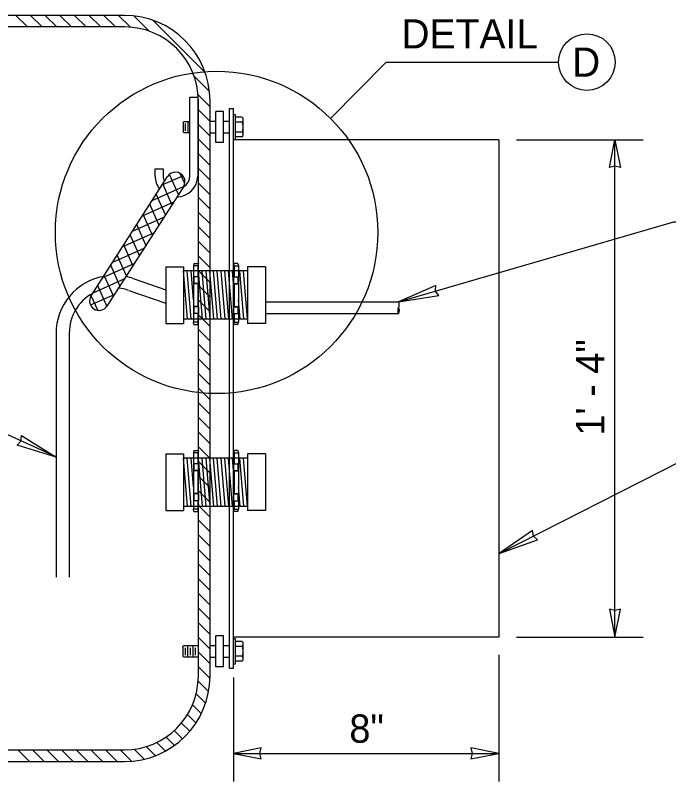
# Model space of a CAD drawing. Extents: x 99862 to 103680, y 99470 to 105076.
# Drawn here: x 100567.9 to 100937.1, y 103401 to 103834.1 of the extents above; entities that cross this region are included whole.
import ezdxf

# ---------------------------------------------------------------- set-up
doc = ezdxf.new("R2010")
doc.units = 0
for name, color, linetype in [('Level 1', 7, 'Continuous'), ('Level 11', 7, 'Continuous'), ('Level 12', 7, 'Continuous'), ('Level 14', 7, 'Continuous'), ('Level 15', 7, 'Continuous'), ('Level 20', 7, 'Continuous'), ('Level 3', 7, 'Continuous'), ('Level 9', 7, 'Continuous')]:
    doc.layers.add(name, color=color, linetype=linetype)

msp = doc.modelspace()

# ---------------------------------------------------------------- linework, layer by layer
at = {"layer": 'Level 1'}
for p, q in [((100634.52, 103685.35), (100652.91, 103679)), ((100631.96, 103678.64), (100652.91, 103671.41)), ((100590.9, 103654.26), (100590.9, 103516.53)), ((100598.4, 103654.73), (100598.4, 103516.53))]:
    msp.add_line(p, q, dxfattribs=at)
for centre, radius, start, end in [((100623.79, 103654.26), 32.89, 100.4692, 180), ((100623.79, 103654.26), 32.89, 70.9545, 78.4399), ((100623.7, 103654.73), 25.3, 70.9545, 84.4128), ((100623.7, 103654.73), 25.3, 118.4861, 180)]:
    msp.add_arc(centre, radius, start, end, dxfattribs=at)
at = {"layer": 'Level 11'}
for p, q in [((100709.22, 103672.2), (100784.48, 103672.2)), ((100709.22, 103665.61), (100784.48, 103665.61))]:
    msp.add_line(p, q, dxfattribs=at)
for centre, start, end in [((100781.49, 103670.63), 330.734, 27.7275), ((100787.38, 103667.33), 150.734, 210.734), ((100781.54, 103667.26), 330.734, 30.734)]:
    msp.add_arc(centre, 3.37, start, end, dxfattribs=at)
at = {"layer": 'Level 12'}
for p, q in [((100629.6, 103834.1), (100304.55, 103834.1)), ((100568.28, 103834.1), (100574.87, 103827.51)), ((100576.57, 103834.1), (100583.16, 103827.51)), ((100584.85, 103834.1), (100591.44, 103827.51)), ((100593.13, 103834.1), (100599.72, 103827.51)), ((100601.42, 103834.1), (100608.01, 103827.51)), ((100609.7, 103834.1), (100616.29, 103827.51)), ((100617.98, 103834.1), (100624.57, 103827.51)), ((100626.26, 103834.1), (100632.99, 103827.38)), ((100634.86, 103833.79), (100643.53, 103825.12)), ((100645.63, 103831.31), (100675.12, 103801.81)), ((100629.6, 103827.51), (100304.55, 103827.51)), ((100668.94, 103799.71), (100677.6, 103791.05)), ((100671.19, 103789.18), (100677.92, 103782.45)), ((100671.33, 103460.73), (100671.33, 103785.78)), ((100677.92, 103460.73), (100677.92, 103785.78)), ((100671.33, 103780.75), (100677.92, 103774.17)), ((100671.33, 103772.47), (100677.92, 103765.88)), ((100671.33, 103764.19), (100677.92, 103757.6)), ((100671.33, 103755.91), (100677.92, 103749.32)), ((100671.33, 103747.62), (100677.92, 103741.03)), ((100671.33, 103739.34), (100677.92, 103732.75)), ((100671.33, 103731.06), (100677.92, 103724.47)), ((100671.33, 103722.77), (100677.92, 103716.19)), ((100671.33, 103714.49), (100677.92, 103707.9)), ((100671.33, 103706.21), (100677.92, 103699.62)), ((100671.33, 103697.93), (100677.92, 103691.34)), ((100671.33, 103689.64), (100677.92, 103683.05)), ((100671.33, 103681.36), (100677.92, 103674.77)), ((100671.33, 103673.08), (100677.92, 103666.49)), ((100671.33, 103664.79), (100677.92, 103658.21)), ((100671.33, 103656.51), (100677.92, 103649.92)), ((100671.33, 103648.23), (100677.92, 103641.64)), ((100671.33, 103639.95), (100677.92, 103633.36)), ((100671.33, 103631.66), (100677.92, 103625.07)), ((100671.33, 103623.38), (100677.92, 103616.79)), ((100671.33, 103615.1), (100677.92, 103608.51)), ((100671.33, 103606.81), (100677.92, 103600.23)), ((100671.33, 103598.53), (100677.92, 103591.94)), ((100671.33, 103590.25), (100677.92, 103583.66)), ((100671.33, 103581.97), (100677.92, 103575.38)), ((100671.33, 103573.68), (100677.92, 103567.09)), ((100671.33, 103565.4), (100677.92, 103558.81)), ((100671.33, 103557.12), (100677.92, 103550.53)), ((100671.33, 103548.83), (100677.92, 103542.25)), ((100671.33, 103540.55), (100677.92, 103533.96)), ((100671.33, 103532.27), (100677.92, 103525.68)), ((100671.33, 103523.99), (100677.92, 103517.4)), ((100671.33, 103515.7), (100677.92, 103509.11)), ((100671.33, 103507.42), (100677.92, 103500.83)), ((100671.33, 103499.14), (100677.92, 103492.55)), ((100671.33, 103490.86), (100677.92, 103484.27)), ((100671.33, 103482.57), (100677.92, 103475.98)), ((100671.33, 103474.29), (100677.92, 103467.7)), ((100671.33, 103466.01), (100677.86, 103459.48)), ((100671.23, 103457.83), (100677.09, 103451.97)), ((100670.1, 103450.67), (100675.37, 103445.4)), ((100668.03, 103444.46), (100672.96, 103439.53)), ((100665.22, 103438.99), (100669.98, 103434.23)), ((100661.77, 103434.15), (100666.43, 103429.49)), ((100657.73, 103429.91), (100662.36, 103425.28)), ((100653.11, 103426.25), (100657.8, 103421.56)), ((100635.14, 103419.37), (100640.74, 103413.77)), ((100641.93, 103420.86), (100647.07, 103415.72)), ((100647.87, 103423.21), (100652.74, 103418.34)), ((100511, 103419), (100629.6, 103419)), ((100569.25, 103419), (100575.84, 103412.41)), ((100577.53, 103419), (100584.12, 103412.41)), ((100585.81, 103419), (100592.4, 103412.41)), ((100594.1, 103419), (100600.68, 103412.41)), ((100602.38, 103419), (100608.97, 103412.41)), ((100610.66, 103419), (100617.25, 103412.41)), ((100618.94, 103419), (100625.53, 103412.41)), ((100627.23, 103419), (100633.63, 103412.6)), ((100304.55, 103412.41), (100629.6, 103412.41))]:
    msp.add_line(p, q, dxfattribs=at)
for centre, radius, start, end in [((100629.6, 103785.78), 48.32, 0, 90), ((100629.6, 103785.78), 41.73, 360, 90), ((100629.6, 103460.73), 41.73, 270, 0), ((100629.6, 103460.73), 48.32, 270, 0)]:
    msp.add_arc(centre, radius, start, end, dxfattribs=at)
at = {"layer": 'Level 14'}
for p, q in [((100688.9, 103781.39), (100691.1, 103781.39)), ((100688.9, 103465.12), (100688.9, 103781.39)), ((100691.1, 103465.12), (100691.1, 103781.39)), ((100841.03, 103763.82), (100691.1, 103763.82)), ((100841.03, 103763.82), (100841.03, 103482.69)), ((100841.03, 103482.69), (100691.1, 103482.69)), ((100688.9, 103465.12), (100691.1, 103465.12))]:
    msp.add_line(p, q, dxfattribs=at)
at = {"layer": 'Level 15'}
for p, q in [((100746.04, 103775.83), (100777.5, 103807.65)), ((100777.5, 103807.65), (100874.85, 103807.65)), ((100851.03, 103763.82), (100922.7, 103763.82)), ((100906.7, 103482.69), (100906.7, 103763.82)), ((100851.03, 103482.69), (100922.7, 103482.69)), ((100841.03, 103472.69), (100841.03, 103401.03)), ((100691.1, 103459.82), (100691.1, 103401.03)), ((100691.1, 103417.03), (100841.03, 103417.03))]:
    msp.add_line(p, q, dxfattribs=at)
for points in [[(100906.7, 103763.82), (100909.79, 103748.1), (100906.7, 103748.83), (100903.62, 103748.1)], [(100784.48, 103672.2), (100807.23, 103675.7), (100805.39, 103678.27), (100805.57, 103681.44)], [(100590.91, 103584.46), (100568.88, 103591.15), (100571.07, 103593.43), (100571.34, 103596.59)], [(100841.21, 103529.97), (100862.92, 103537.64), (100860.63, 103539.82), (100860.22, 103542.96)], [(100906.7, 103482.69), (100909.79, 103498.42), (100906.7, 103497.69), (100903.62, 103498.42)], [(100691.1, 103417.03), (100706.82, 103413.94), (100706.1, 103417.03), (100706.82, 103420.11)], [(100841.03, 103417.03), (100825.31, 103420.11), (100826.04, 103417.03), (100825.31, 103413.94)]]:
    msp.add_lwpolyline(points, close=True, dxfattribs=at)
for points in [[(100784.48, 103672.2), (100939.99, 103717.38), (100955.99, 103717.38)], [(100590.9, 103584.52), (100496.42, 103627.61), (100482.42, 103627.61)], [(100841.21, 103529.97), (100944.34, 103582.32), (100955.99, 103582.32)]]:
    msp.add_lwpolyline(points, dxfattribs=at)
msp.add_circle((100681.63, 103711.42), 91.09, dxfattribs=at)
at = {"layer": 'Level 20'}
msp.add_circle((100890.85, 103807.65), 16, dxfattribs=at)
at = {"layer": 'Level 3'}
for p, q in [((100666.48, 103743.25), (100666.48, 103787.94)), ((100666.48, 103787.94), (100671.04, 103787.94)), ((100671.04, 103787.94), (100671.04, 103743.25)), ((100681.21, 103762.17), (100681.21, 103779.74)), ((100685.61, 103779.74), (100681.21, 103779.74)), ((100685.61, 103762.17), (100685.61, 103779.74)), ((100685.61, 103762.17), (100681.21, 103762.17)), ((100646.88, 103747.37), (100651.43, 103747.37)), ((100651.43, 103747.37), (100651.43, 103743.25)), ((100660.11, 103732.88), (100655.08, 103744.2)), ((100663.61, 103739.03), (100661.1, 103744.68)), ((100610.73, 103675.55), (100653.96, 103743.01)), ((100650.91, 103738.24), (100662.56, 103743.43)), ((100662.92, 103737.26), (100619.69, 103669.8)), ((100645.32, 103729.53), (100662.97, 103737.38)), ((100656.44, 103727.14), (100651.25, 103738.79)), ((100652.76, 103721.4), (100647.58, 103733.05)), ((100639.74, 103720.81), (100657.42, 103728.68)), ((100649.08, 103715.66), (100643.9, 103727.31)), ((100634.15, 103712.1), (100651.84, 103719.97)), ((100645.4, 103709.92), (100640.22, 103721.57)), ((100641.72, 103704.18), (100636.54, 103715.83)), ((100628.57, 103703.38), (100646.25, 103711.25)), ((100638.05, 103698.45), (100632.87, 103710.09)), ((100622.98, 103694.67), (100640.67, 103702.54)), ((100634.37, 103692.71), (100629.19, 103704.35)), ((100630.69, 103686.97), (100625.51, 103698.61)), ((100617.4, 103685.96), (100635.08, 103693.82)), ((100627.01, 103681.23), (100621.83, 103692.88)), ((100668.84, 103693.94), (100668.55, 103692.55)), ((100668.55, 103692.55), (100668.55, 103660.78)), ((100671.04, 103692.55), (100668.55, 103692.55)), ((100668.84, 103693.94), (100671.33, 103693.94)), ((100671.33, 103693.94), (100671.04, 103692.55)), ((100671.04, 103692.55), (100671.04, 103686.41)), ((100693.71, 103693.94), (100691.22, 103693.94)), ((100691.22, 103693.94), (100691.51, 103692.55)), ((100691.51, 103692.55), (100691.51, 103686.41)), ((100691.51, 103692.55), (100694, 103692.55)), ((100693.71, 103693.94), (100694, 103692.55)), ((100694, 103692.55), (100694, 103660.78)), ((100652.91, 103691.98), (100662.98, 103691.98)), ((100652.91, 103691.98), (100652.91, 103659.95)), ((100665.21, 103662.32), (100662.96, 103689.62)), ((100662.98, 103691.98), (100662.98, 103659.95)), ((100699.15, 103689.62), (100662.98, 103689.62)), ((100667.33, 103662.32), (100665.08, 103689.62)), ((100668.55, 103673.29), (100667.2, 103689.62)), ((100673.7, 103662.32), (100671.45, 103689.62)), ((100675.82, 103662.32), (100673.57, 103689.62)), ((100677.94, 103662.32), (100675.69, 103689.62)), ((100680.06, 103662.32), (100677.81, 103689.62)), ((100682.18, 103662.32), (100679.93, 103689.62)), ((100684.3, 103662.32), (100682.05, 103689.62)), ((100686.43, 103662.32), (100684.18, 103689.62)), ((100688.55, 103662.32), (100686.3, 103689.62)), ((100690.67, 103662.32), (100688.42, 103689.62)), ((100691.51, 103677.85), (100690.54, 103689.62)), ((100697.03, 103662.32), (100694.78, 103689.62)), ((100699.15, 103662.32), (100696.9, 103689.62)), ((100709.22, 103691.98), (100699.15, 103691.98)), ((100699.15, 103691.98), (100699.15, 103659.95)), ((100709.22, 103691.98), (100709.22, 103659.95)), ((100611.81, 103677.24), (100629.5, 103685.11)), ((100623.33, 103675.49), (100618.15, 103687.14)), ((100668.55, 103686.12), (100668.84, 103686.41)), ((100668.84, 103686.41), (100668.84, 103682.61)), ((100671.33, 103686.41), (100668.84, 103686.41)), ((100671.33, 103686.41), (100671.33, 103682.61)), ((100691.22, 103686.41), (100691.22, 103682.61)), ((100691.22, 103686.41), (100693.71, 103686.41)), ((100693.71, 103686.41), (100693.71, 103682.61)), ((100694, 103686.12), (100693.71, 103686.41)), ((100619.65, 103669.76), (100614.48, 103681.4)), ((100668.84, 103682.61), (100668.55, 103682.32)), ((100671.04, 103682.32), (100668.55, 103682.32)), ((100671.33, 103682.61), (100668.84, 103682.61)), ((100671.33, 103682.61), (100671.04, 103682.32)), ((100671.04, 103682.32), (100671.04, 103669.62)), ((100691.22, 103682.61), (100693.71, 103682.61)), ((100691.22, 103682.61), (100691.51, 103682.32)), ((100691.51, 103682.32), (100694, 103682.32)), ((100691.51, 103682.32), (100691.51, 103669.62)), ((100693.71, 103682.61), (100694, 103682.32)), ((100610.45, 103670.41), (100623.91, 103676.39)), ((100614.45, 103667.44), (100610.8, 103675.66)), ((100694.91, 103662.32), (100694, 103673.39)), ((100671.04, 103669.62), (100668.55, 103669.62)), ((100668.84, 103669.33), (100668.55, 103669.62)), ((100671.33, 103669.33), (100668.84, 103669.33)), ((100668.84, 103669.33), (100668.84, 103665.53)), ((100671.33, 103669.33), (100671.04, 103669.62)), ((100671.33, 103669.33), (100671.33, 103665.53)), ((100691.22, 103669.33), (100691.51, 103669.62)), ((100691.22, 103669.33), (100693.71, 103669.33)), ((100691.22, 103669.33), (100691.22, 103665.53)), ((100691.51, 103669.62), (100694, 103669.62)), ((100693.71, 103669.33), (100694, 103669.62)), ((100693.71, 103669.33), (100693.71, 103665.53)), ((100699.15, 103662.32), (100662.98, 103662.32)), ((100668.55, 103665.82), (100668.84, 103665.53)), ((100671.33, 103665.53), (100668.84, 103665.53)), ((100671.04, 103665.53), (100671.04, 103660.78)), ((100671.58, 103662.32), (100671.33, 103665.28)), ((100691.22, 103665.53), (100693.71, 103665.53)), ((100691.51, 103665.53), (100691.51, 103660.78)), ((100694, 103665.82), (100693.71, 103665.53)), ((100652.91, 103659.95), (100662.98, 103659.95)), ((100671.04, 103660.78), (100668.55, 103660.78)), ((100668.84, 103659.39), (100668.55, 103660.78)), ((100668.84, 103659.39), (100671.33, 103659.39)), ((100671.33, 103659.39), (100671.04, 103660.78)), ((100691.22, 103659.39), (100691.51, 103660.78)), ((100693.71, 103659.39), (100691.22, 103659.39)), ((100691.51, 103660.78), (100694, 103660.78)), ((100693.71, 103659.39), (100694, 103660.78)), ((100709.22, 103659.95), (100699.15, 103659.95)), ((100668.84, 103588.24), (100668.55, 103586.85)), ((100668.84, 103588.24), (100671.33, 103588.24)), ((100671.33, 103588.24), (100671.04, 103586.85)), ((100693.71, 103588.24), (100691.22, 103588.24)), ((100691.22, 103588.24), (100691.51, 103586.85)), ((100693.71, 103588.24), (100694, 103586.85)), ((100652.91, 103586.28), (100662.98, 103586.28)), ((100652.91, 103586.28), (100652.91, 103554.25)), ((100665.21, 103556.61), (100662.96, 103583.92)), ((100662.98, 103586.28), (100662.98, 103554.25)), ((100699.15, 103583.92), (100662.98, 103583.92)), ((100667.33, 103556.61), (100665.08, 103583.92)), ((100668.55, 103567.59), (100667.2, 103583.92)), ((100668.55, 103586.85), (100668.55, 103555.07)), ((100671.04, 103586.85), (100668.55, 103586.85)), ((100671.04, 103586.85), (100671.04, 103580.7)), ((100673.7, 103556.61), (100671.45, 103583.92)), ((100675.82, 103556.61), (100673.57, 103583.92)), ((100677.94, 103556.61), (100675.69, 103583.92)), ((100680.06, 103556.61), (100677.81, 103583.92)), ((100682.18, 103556.61), (100679.93, 103583.92)), ((100684.3, 103556.61), (100682.05, 103583.92)), ((100686.43, 103556.61), (100684.18, 103583.92)), ((100688.55, 103556.61), (100686.3, 103583.92)), ((100690.67, 103556.61), (100688.42, 103583.92)), ((100691.51, 103572.15), (100690.54, 103583.92)), ((100691.51, 103586.85), (100691.51, 103580.7)), ((100691.51, 103586.85), (100694, 103586.85)), ((100694, 103586.85), (100694, 103555.07)), ((100697.03, 103556.61), (100694.78, 103583.92)), ((100699.15, 103556.61), (100696.9, 103583.92)), ((100709.22, 103586.28), (100699.15, 103586.28)), ((100699.15, 103586.28), (100699.15, 103554.25)), ((100709.22, 103586.28), (100709.22, 103554.25)), ((100668.55, 103580.41), (100668.84, 103580.7)), ((100668.84, 103580.7), (100668.84, 103576.9)), ((100671.33, 103580.7), (100668.84, 103580.7)), ((100671.33, 103580.7), (100671.33, 103576.9)), ((100691.22, 103580.7), (100691.22, 103576.9)), ((100691.22, 103580.7), (100693.71, 103580.7)), ((100693.71, 103580.7), (100693.71, 103576.9)), ((100694, 103580.41), (100693.71, 103580.7)), ((100668.84, 103576.9), (100668.55, 103576.61)), ((100671.04, 103576.61), (100668.55, 103576.61)), ((100671.33, 103576.9), (100668.84, 103576.9)), ((100671.33, 103576.9), (100671.04, 103576.61)), ((100671.04, 103576.61), (100671.04, 103563.92)), ((100691.22, 103576.9), (100693.71, 103576.9)), ((100691.22, 103576.9), (100691.51, 103576.61)), ((100691.51, 103576.61), (100694, 103576.61)), ((100691.51, 103576.61), (100691.51, 103563.92)), ((100693.71, 103576.9), (100694, 103576.61)), ((100694.91, 103556.61), (100694, 103567.69)), ((100671.04, 103563.92), (100668.55, 103563.92)), ((100668.84, 103563.62), (100668.55, 103563.92)), ((100671.33, 103563.62), (100668.84, 103563.62)), ((100668.84, 103563.62), (100668.84, 103559.82)), ((100671.33, 103563.62), (100671.04, 103563.92)), ((100671.33, 103563.62), (100671.33, 103559.82)), ((100691.22, 103563.62), (100691.51, 103563.92)), ((100691.22, 103563.62), (100693.71, 103563.62)), ((100691.22, 103563.62), (100691.22, 103559.82)), ((100691.51, 103563.92), (100694, 103563.92)), ((100693.71, 103563.62), (100694, 103563.92)), ((100693.71, 103563.62), (100693.71, 103559.82)), ((100668.55, 103560.12), (100668.84, 103559.82)), ((100671.33, 103559.82), (100668.84, 103559.82)), ((100671.04, 103559.82), (100671.04, 103555.07)), ((100671.58, 103556.61), (100671.33, 103559.57)), ((100691.22, 103559.82), (100693.71, 103559.82)), ((100691.51, 103559.82), (100691.51, 103555.07)), ((100694, 103560.12), (100693.71, 103559.82)), ((100652.91, 103554.25), (100662.98, 103554.25)), ((100699.15, 103556.61), (100662.98, 103556.61)), ((100671.04, 103555.07), (100668.55, 103555.07)), ((100668.84, 103553.68), (100668.55, 103555.07)), ((100668.84, 103553.68), (100671.33, 103553.68)), ((100671.33, 103553.68), (100671.04, 103555.07)), ((100691.22, 103553.68), (100691.51, 103555.07)), ((100693.71, 103553.68), (100691.22, 103553.68)), ((100691.51, 103555.07), (100694, 103555.07)), ((100693.71, 103553.68), (100694, 103555.07)), ((100709.22, 103554.25), (100699.15, 103554.25)), ((100681.21, 103465.89), (100681.21, 103483.46)), ((100685.61, 103483.46), (100681.21, 103483.46)), ((100685.61, 103465.89), (100685.61, 103483.46)), ((100685.61, 103465.89), (100681.21, 103465.89))]:
    msp.add_line(p, q, dxfattribs=at)
msp.add_lwpolyline([(100646.88, 103743.25), (100646.88, 103747.37)], dxfattribs=at)
for centre, radius, start, end in [((100658.44, 103740.13), 5.32, 327.3459, 147.3459), ((100658.26, 103743.25), 11.39, 180, 219.4747), ((100658.26, 103743.25), 6.83, 180, 206.5845), ((100658.82, 103743.63), 12.22, 271.6541, 358.1977), ((100659.65, 103743.25), 6.83, 298.9346, 360), ((100615.21, 103672.67), 5.32, 147.3459, 327.3459)]:
    msp.add_arc(centre, radius, start, end, dxfattribs=at)
at = {"layer": 'Level 9'}
for p, q in [((100696.05, 103776.55), (100692.18, 103776.55)), ((100696.05, 103776.55), (100696.48, 103775.8)), ((100696.48, 103775.8), (100696.48, 103775.22)), ((100696.48, 103775.22), (100696.48, 103775.08)), ((100696.48, 103775.08), (100696.48, 103771.07)), ((100662.71, 103773.4), (100663.17, 103774.18)), ((100662.71, 103773.4), (100662.71, 103768.49)), ((100663.17, 103774.18), (100666.48, 103774.18)), ((100664.15, 103768.89), (100664.15, 103773.01)), ((100665.58, 103767.72), (100665.58, 103774.18)), ((100677.92, 103774.25), (100681.21, 103774.25)), ((100685.61, 103774.25), (100688.9, 103774.25)), ((100696.05, 103773.75), (100692.18, 103773.75)), ((100696.48, 103771.07), (100696.48, 103770.83)), ((100696.48, 103770.83), (100696.48, 103766.79)), ((100663.16, 103767.72), (100662.71, 103768.49)), ((100666.48, 103767.72), (100663.16, 103767.72)), ((100677.92, 103767.66), (100681.21, 103767.66)), ((100685.61, 103767.66), (100688.9, 103767.66)), ((100696.05, 103768.16), (100692.18, 103768.16)), ((100696.48, 103766.11), (100696.05, 103765.36)), ((100696.48, 103766.79), (100696.48, 103766.73)), ((100696.48, 103766.73), (100696.48, 103766.11)), ((100696.05, 103765.36), (100692.18, 103765.36)), ((100696.05, 103480.27), (100692.18, 103480.27)), ((100696.05, 103480.27), (100696.48, 103479.52)), ((100662.57, 103477.12), (100663.02, 103477.9)), ((100662.57, 103477.12), (100662.57, 103472.2)), ((100663.02, 103477.9), (100671.18, 103477.9)), ((100664, 103472.61), (100664, 103476.73)), ((100665.44, 103471.44), (100665.44, 103477.9)), ((100666.87, 103472.61), (100666.87, 103476.73)), ((100668.31, 103471.44), (100668.31, 103477.9)), ((100669.74, 103472.61), (100669.74, 103476.73)), ((100677.92, 103477.97), (100681.21, 103477.97)), ((100685.61, 103477.97), (100688.9, 103477.97)), ((100696.05, 103477.47), (100692.18, 103477.47)), ((100696.48, 103479.52), (100696.48, 103478.93)), ((100696.48, 103478.93), (100696.48, 103478.8)), ((100696.48, 103478.8), (100696.48, 103474.79)), ((100663.01, 103471.44), (100662.57, 103472.2)), ((100671.18, 103471.44), (100663.01, 103471.44)), ((100677.92, 103471.38), (100681.21, 103471.38)), ((100685.61, 103471.38), (100688.9, 103471.38)), ((100696.05, 103471.87), (100692.18, 103471.87)), ((100696.48, 103474.79), (100696.48, 103474.55)), ((100696.48, 103474.55), (100696.48, 103470.51)), ((100696.05, 103469.07), (100692.18, 103469.07)), ((100696.48, 103469.82), (100696.05, 103469.07)), ((100696.48, 103470.51), (100696.48, 103470.44)), ((100696.48, 103470.44), (100696.48, 103469.82))]:
    msp.add_line(p, q, dxfattribs=at)
for points in [[(100691.1, 103763.77), (100691.1, 103778.13), (100692.18, 103778.13), (100692.18, 103763.77)], [(100691.1, 103467.49), (100691.1, 103481.85), (100692.18, 103481.85), (100692.18, 103467.49)]]:
    msp.add_lwpolyline(points, close=True, dxfattribs=at)
for points, degree in [([(100696.06, 103776.54), (100696.05, 103776.54), (100696.05, 103776.55), (100696.05, 103776.55)], 2), ([(100696.05, 103776.55), (100696.3, 103776.11), (100696.47, 103775.67), (100696.48, 103775.22)], 2), ([(100696.48, 103775.08), (100696.47, 103774.63), (100696.3, 103774.19), (100696.05, 103773.75)], 2), ([(100696.05, 103773.75), (100696.18, 103773.32), (100696.28, 103772.87), (100696.43, 103771.98), (100696.48, 103771.53), (100696.48, 103771.07)], 3), ([(100696.48, 103770.83), (100696.48, 103770.38), (100696.43, 103769.92), (100696.28, 103769.03), (100696.18, 103768.59), (100696.05, 103768.16)], 3), ([(100696.05, 103768.16), (100696.31, 103767.71), (100696.48, 103767.25), (100696.48, 103766.79)], 2), ([(100696.48, 103766.72), (100696.48, 103766.49), (100696.44, 103766.26), (100696.29, 103765.81), (100696.18, 103765.58), (100696.05, 103765.36)], 3), ([(100696.06, 103480.26), (100696.05, 103480.26), (100696.05, 103480.26), (100696.05, 103480.27)], 2), ([(100696.05, 103480.27), (100696.3, 103479.83), (100696.47, 103479.39), (100696.48, 103478.93)], 2), ([(100696.48, 103478.8), (100696.47, 103478.35), (100696.3, 103477.9), (100696.05, 103477.47)], 2), ([(100696.05, 103477.47), (100696.18, 103477.03), (100696.28, 103476.59), (100696.43, 103475.69), (100696.48, 103475.24), (100696.48, 103474.79)], 3), ([(100696.48, 103474.55), (100696.48, 103474.1), (100696.43, 103473.64), (100696.28, 103472.74), (100696.18, 103472.31), (100696.05, 103471.87)], 3), ([(100696.05, 103471.87), (100696.31, 103471.43), (100696.48, 103470.97), (100696.48, 103470.51)], 2), ([(100696.48, 103470.44), (100696.48, 103470.21), (100696.44, 103469.98), (100696.29, 103469.52), (100696.18, 103469.3), (100696.05, 103469.07)], 3)]:
    msp.add_open_spline(points, degree=degree, dxfattribs=at)

# ---------------------------------------------------------------- texts
at = {"layer": 'Level 20'}
for s, height, p in [('DETAIL', 16.5, (100786.02, 103815.4)), ('D', 16.5, (100882.45, 103799.4)), ('8"', 16, (100756.65, 103423.03))]:
    msp.add_text(s, height=height, dxfattribs=at).set_placement(p)
msp.add_text('1\' - 4"', height=16, rotation=90, dxfattribs=at).set_placement((100900.7, 103596.57))

doc.saveas('drawing.dxf')
